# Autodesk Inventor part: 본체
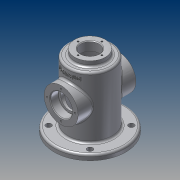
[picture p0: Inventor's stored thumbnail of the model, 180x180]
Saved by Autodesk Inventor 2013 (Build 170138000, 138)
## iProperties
Created: 2014-12
Part Number: 본체
Material: 알루미늄 6061
Document SubType Name: Modeling
Designer: CAD-B27
Density: 2.71 g/cm^3
Mass: 478.598 g
Surface Area: 607.666 cm^2
Volume: 176.604 cm^3
Author: CAD-B27
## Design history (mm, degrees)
sketch "스케치1"
  geometry: L1 (0, 43)-(-32.5, 43); L2 (-32.5, 43)-(-32.5, -47); L3 (-32.5, -47)-(0, -47); L4 (0, -47)-(0, 43); 1 further point
  constraints: 8 end point, 2 parallel, 1 horizontal, 1 perpendicular, 1 point on line
  dimensions: "d0" = 65 diameter of L2 L4; "d2" = 47 distance from line of L3 point (0, 0); "d3" = 90 distance of L1.end L2.end
revolve "회전1" sketch "스케치1" stored, may be unused: angle "d4" = 90 deg
sketch "스케치2"
  geometry: L1 (32.5, -47)-(-32.5, -47) reference; L2 (-32.5, -47)-(-32.5, 43) reference; L3 (-32.5, 43)-(32.5, 43) reference; L4 (32.5, 43)-(32.5, -47) reference; C1 r 25 at (0, 0); 1 further point
  constraints: 1 centre point, 1 coincident
  dimensions: "d5" = 50 diameter of C1
extrude "돌출1" join sketch "스케치2" stored distance "d7" = 85; taper "d8" = 0 deg
sketch "스케치3"
  geometry: C1 r 32.5 at (0, 0) reference; C2 r 22.5 at (0, 0)
  constraints: 1 centre point, 1 coincident
  dimensions: "d9" = 45 diameter of C2
extrude "돌출2" join sketch "스케치3" distance "d10" = 8; taper "d11" = 0 deg
sketch "스케치4"
  geometry: C1 r 32.5 at (0, 0) reference; C2 r 52.5 at (0, 0)
  constraints: 1 centre point, 1 coincident
  dimensions: "d12" = 105 diameter of C2
extrude "돌출3" join sketch "스케치4" distance "d13" = 8; taper "d14" = 0 deg
hole "구멍1" diameter "d17" = 27; stored, may be unused: countersink angle "d21" = 90 deg, drill point angle "d23" = 118 deg; dims "d15" = 10, "d16" = 10, "d18" = 6, "d19" = 55, "d20" = 93, "d22" = 8
hole "구멍2" diameter "d26" = 25; stored, may be unused: countersink angle "d30" = 90 deg, drill point angle "d32" = 118 deg; dims "d24" = 10, "d25" = 10, "d27" = 6, "d28" = 32, "d29" = 12, "d31" = 8
hole "구멍3" diameter "d35" = 32; stored, may be unused: countersink angle "d39" = 90 deg, drill point angle "d41" = 0 deg; dims "d33" = 10, "d34" = 10, "d36" = 6, "d37" = 32, "d38" = 12, "d40" = 12
sketch "스케치5"
  geometry: C1 r 16 at (0, 0) reference; 1 further point
  constraints: 1 vertical alignment
  dimensions: "d42" = 20.5 distance of C1.centre point (0, 20.5)
hole "구멍4" sketch "스케치5" at (0, 20.5) diameter "d43" = 2.459; stored, may be unused: countersink angle "d47" = 90 deg, drill point angle "d49" = 118 deg; dims "d44" = 6, "d45" = 32, "d46" = 12, "d48" = 8
sketch "스케치6"
  geometry: C1 r 13.5 at (0, 0) reference; 1 further point
  constraints: 1 vertical alignment
  dimensions: "d53" = 17.5 distance of C1.centre point (0, 17.5)
hole "구멍5" sketch "스케치6" at (0, 17.5) diameter "d54" = 2.459; stored, may be unused: countersink angle "d58" = 90 deg, drill point angle "d60" = 118 deg; dims "d55" = 6, "d56" = 32, "d57" = 12, "d59" = 8
sketch "스케치7"
  geometry: L1 (0, 52.5)-(0, 0); L2 (0, 0)-(37.123, 37.123); C1 r 52.5 at (0, 0) reference; C2 r 27.5 at (0, 0) reference; C3 r 32.5 at (0, 0) reference; A1 r 52.5 centre (0, 0) between (0, 52.5) and (37.123, 37.123) reference; 1 further point
  constraints: 4 end point, 2 point on circle, 1 coincident, 1 point on line, 1 vertical
  dimensions: "d64" = 45 deg angle of L2 L1; "d65" = 43 distance of C1.centre point (30.406, 30.406)
hole "구멍6" sketch "스케치7" at (30.406, 30.406) diameter "d66" = 8; stored, may be unused: countersink angle "d70" = 90 deg, drill point angle "d72" = 118 deg; dims "d67" = 6, "d68" = 32, "d69" = 12, "d71" = 8
chamfer "모따기1" distance "d76" = 1; stored, may be unused: second distance "d77" = 2, angle "d78" = 45 deg
fillet "모깎기1" dims "d79" = 3
fillet "모깎기2" dims "d80" = 0.3
node "작업 평면1"
sketch "스케치8"
  geometry: L1 (-16.592, 36.402)-(16.592, 36.402); L2 (16.592, 36.402)-(16.592, 31.598); L3 (16.592, 31.598)-(-16.592, 31.598); L4 (-16.592, 31.598)-(-16.592, 36.402); L5 (-29.5, 43)-(29.5, 43) reference; 3 further points
  constraints: 2 midpoint, 1 vertical alignment, 2 other
  dimensions: "d82" = 9 distance from line of point (-16.592, 34) L5
feature "엠보싱1" sketch "스케치8" dims "d0" = 65, "d2" = 47, "d3" = 90, "d83" = 1, "d84" = 0
node "솔리드1"
pattern_circular "원형 패턴1" dims angle "d51" = 360 deg
mirror "대칭1"
pattern_circular "원형 패턴2" dims angle "d62" = 360 deg
pattern_circular "원형 패턴3" dims angle "d74" = 360 deg
node "절단 모서리 투영1"
node "절단 모서리 투영2"
other parameters: "d81" = 39.5
